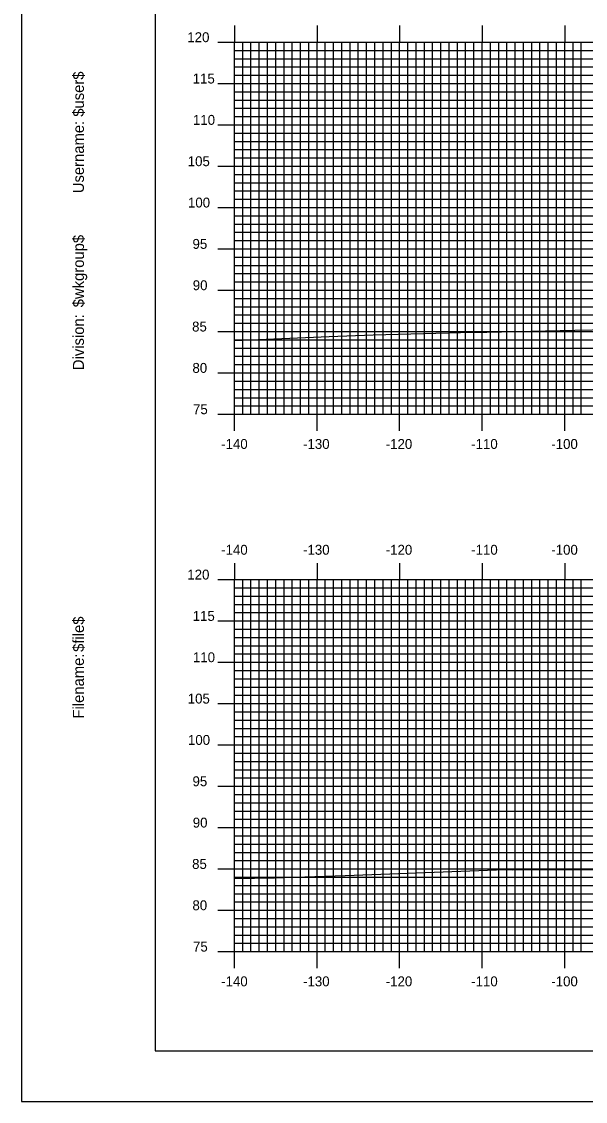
# Model space of a CAD drawing. Extents: x 485 to 829, y -1658 to -1438.
# Drawn here: x 485.3 to 553.6, y -1657.7 to -1527.1 of the extents above; entities that cross this region are included whole.
import ezdxf

# ---------------------------------------------------------------- set-up
doc = ezdxf.new("R2010")
doc.units = 0
for name, color, linetype in [('BORDER', 7, 'Continuous'), ('H_V ANNOTATION', 7, 'Continuous'), ('MAJOR', 7, 'Continuous'), ('MINOR', 7, 'Continuous'), ('PLOT BOUNDARY', 7, 'Continuous'), ('S_Roadway_Centerline', 7, 'Continuous')]:
    doc.layers.add(name, color=color, linetype=linetype)

msp = doc.modelspace()

# ---------------------------------------------------------------- linework, layer by layer
at = {"layer": 'BORDER'}
msp.add_lwpolyline([(501.53, -1651.6), (821.53, -1651.6), (821.53, -1441.6), (501.53, -1441.6)], close=True, dxfattribs=at)
at = {"layer": 'MAJOR'}
for p, q in [((511.13, -1527.6), (511.13, -1529.6)), ((521.13, -1527.6), (521.13, -1529.6)), ((531.13, -1527.6), (531.13, -1529.6)), ((541.13, -1527.6), (541.13, -1529.6)), ((551.13, -1527.6), (551.13, -1529.6)), ((509.13, -1529.6), (511.13, -1529.6)), ((511.13, -1529.6), (791.13, -1529.6)), ((511.13, -1574.6), (511.13, -1529.6)), ((511.13, -1574.6), (511.13, -1529.6)), ((511.13, -1529.6), (791.13, -1529.6)), ((521.13, -1574.6), (521.13, -1529.6)), ((531.13, -1574.6), (531.13, -1529.6)), ((541.13, -1574.6), (541.13, -1529.6)), ((551.13, -1574.6), (551.13, -1529.6)), ((509.13, -1534.6), (511.13, -1534.6)), ((511.13, -1534.6), (791.13, -1534.6)), ((509.13, -1539.6), (511.13, -1539.6)), ((511.13, -1539.6), (791.13, -1539.6)), ((509.13, -1544.6), (511.13, -1544.6)), ((511.13, -1544.6), (791.13, -1544.6)), ((509.13, -1549.6), (511.13, -1549.6)), ((511.13, -1549.6), (791.13, -1549.6)), ((509.13, -1554.6), (511.13, -1554.6)), ((511.13, -1554.6), (791.13, -1554.6)), ((509.13, -1559.6), (511.13, -1559.6)), ((511.13, -1559.6), (791.13, -1559.6)), ((509.13, -1564.6), (511.13, -1564.6)), ((511.13, -1564.6), (791.13, -1564.6)), ((509.13, -1569.6), (511.13, -1569.6)), ((511.13, -1569.6), (791.13, -1569.6)), ((509.13, -1574.6), (511.13, -1574.6)), ((511.13, -1574.6), (791.13, -1574.6)), ((511.13, -1574.6), (791.13, -1574.6)), ((511.13, -1576.61), (511.13, -1574.6)), ((521.13, -1576.61), (521.13, -1574.6)), ((531.13, -1576.61), (531.13, -1574.6)), ((541.13, -1576.61), (541.13, -1574.6)), ((551.13, -1576.61), (551.13, -1574.6)), ((511.13, -1592.6), (511.13, -1594.6)), ((521.13, -1592.6), (521.13, -1594.6)), ((531.13, -1592.6), (531.13, -1594.6)), ((541.13, -1592.6), (541.13, -1594.6)), ((551.13, -1592.6), (551.13, -1594.6)), ((509.13, -1594.6), (511.13, -1594.6)), ((511.13, -1594.6), (791.13, -1594.6)), ((511.13, -1639.6), (511.13, -1594.6)), ((511.13, -1639.6), (511.13, -1594.6)), ((511.13, -1594.6), (791.13, -1594.6)), ((521.13, -1639.6), (521.13, -1594.6)), ((531.13, -1639.6), (531.13, -1594.6)), ((541.13, -1639.6), (541.13, -1594.6)), ((551.13, -1639.6), (551.13, -1594.6)), ((509.13, -1599.6), (511.13, -1599.6)), ((511.13, -1599.6), (791.13, -1599.6)), ((509.13, -1604.6), (511.13, -1604.6)), ((511.13, -1604.6), (791.13, -1604.6)), ((509.13, -1609.6), (511.13, -1609.6)), ((511.13, -1609.6), (791.13, -1609.6)), ((509.13, -1614.6), (511.13, -1614.6)), ((511.13, -1614.6), (791.13, -1614.6)), ((509.13, -1619.6), (511.13, -1619.6)), ((511.13, -1619.6), (791.13, -1619.6)), ((509.13, -1624.6), (511.13, -1624.6)), ((511.13, -1624.6), (791.13, -1624.6)), ((509.13, -1629.6), (511.13, -1629.6)), ((511.13, -1629.6), (791.13, -1629.6)), ((509.13, -1634.6), (511.13, -1634.6)), ((511.13, -1634.6), (791.13, -1634.6)), ((509.13, -1639.6), (511.13, -1639.6)), ((511.13, -1639.6), (791.13, -1639.6)), ((511.13, -1639.6), (791.13, -1639.6)), ((511.13, -1641.61), (511.13, -1639.6)), ((521.13, -1641.61), (521.13, -1639.6)), ((531.13, -1641.61), (531.13, -1639.6)), ((541.13, -1641.61), (541.13, -1639.6)), ((551.13, -1641.61), (551.13, -1639.6))]:
    msp.add_line(p, q, dxfattribs=at)
at = {"layer": 'MINOR'}
for p, q in [((511.13, -1530.6), (791.13, -1530.6)), ((511.13, -1530.6), (513.14, -1530.6)), ((512.13, -1574.6), (512.13, -1529.6)), ((513.13, -1574.6), (513.13, -1529.6)), ((514.13, -1574.6), (514.13, -1529.6)), ((515.13, -1574.6), (515.13, -1529.6)), ((516.13, -1574.6), (516.13, -1529.6)), ((517.13, -1574.6), (517.13, -1529.6)), ((518.13, -1574.6), (518.13, -1529.6)), ((519.13, -1574.6), (519.13, -1529.6)), ((520.13, -1574.6), (520.13, -1529.6)), ((522.13, -1574.6), (522.13, -1529.6)), ((523.13, -1574.6), (523.13, -1529.6)), ((524.13, -1574.6), (524.13, -1529.6)), ((525.13, -1574.6), (525.13, -1529.6)), ((526.13, -1574.6), (526.13, -1529.6)), ((527.13, -1574.6), (527.13, -1529.6)), ((528.13, -1574.6), (528.13, -1529.6)), ((529.13, -1574.6), (529.13, -1529.6)), ((530.13, -1574.6), (530.13, -1529.6)), ((532.13, -1574.6), (532.13, -1529.6)), ((533.13, -1574.6), (533.13, -1529.6)), ((534.13, -1574.6), (534.13, -1529.6)), ((535.13, -1574.6), (535.13, -1529.6)), ((536.13, -1574.6), (536.13, -1529.6)), ((537.13, -1574.6), (537.13, -1529.6)), ((538.13, -1574.6), (538.13, -1529.6)), ((539.13, -1574.6), (539.13, -1529.6)), ((540.13, -1574.6), (540.13, -1529.6)), ((542.13, -1574.6), (542.13, -1529.6)), ((543.13, -1574.6), (543.13, -1529.6)), ((544.13, -1574.6), (544.13, -1529.6)), ((545.13, -1574.6), (545.13, -1529.6)), ((546.13, -1574.6), (546.13, -1529.6)), ((547.13, -1574.6), (547.13, -1529.6)), ((548.13, -1574.6), (548.13, -1529.6)), ((549.13, -1574.6), (549.13, -1529.6)), ((550.13, -1574.6), (550.13, -1529.6)), ((552.13, -1574.6), (552.13, -1529.6)), ((553.13, -1574.6), (553.13, -1529.6)), ((511.13, -1531.6), (791.13, -1531.6)), ((511.13, -1531.6), (513.14, -1531.6)), ((511.13, -1532.6), (791.13, -1532.6)), ((511.13, -1532.6), (513.14, -1532.6)), ((511.13, -1533.6), (791.13, -1533.6)), ((511.13, -1533.6), (513.14, -1533.6)), ((511.13, -1535.6), (791.13, -1535.6)), ((511.13, -1535.6), (513.14, -1535.6)), ((511.13, -1536.6), (791.13, -1536.6)), ((511.13, -1536.6), (513.14, -1536.6)), ((511.13, -1537.6), (791.13, -1537.6)), ((511.13, -1537.6), (513.14, -1537.6)), ((511.13, -1538.6), (791.13, -1538.6)), ((511.13, -1538.6), (513.14, -1538.6)), ((511.13, -1540.6), (791.13, -1540.6)), ((511.13, -1540.6), (513.14, -1540.6)), ((511.13, -1541.6), (791.13, -1541.6)), ((511.13, -1541.6), (513.14, -1541.6)), ((511.13, -1542.6), (791.13, -1542.6)), ((511.13, -1542.6), (513.14, -1542.6)), ((511.13, -1543.6), (791.13, -1543.6)), ((511.13, -1543.6), (513.14, -1543.6)), ((511.13, -1545.6), (791.13, -1545.6)), ((511.13, -1545.6), (513.14, -1545.6)), ((511.13, -1546.6), (791.13, -1546.6)), ((511.13, -1546.6), (513.14, -1546.6)), ((511.13, -1547.6), (791.13, -1547.6)), ((511.13, -1547.6), (513.14, -1547.6)), ((511.13, -1548.6), (791.13, -1548.6)), ((511.13, -1548.6), (513.14, -1548.6)), ((511.13, -1550.6), (791.13, -1550.6)), ((511.13, -1550.6), (513.14, -1550.6)), ((511.13, -1551.6), (791.13, -1551.6)), ((511.13, -1551.6), (513.14, -1551.6)), ((511.13, -1552.6), (791.13, -1552.6)), ((511.13, -1552.6), (513.14, -1552.6)), ((511.13, -1553.6), (791.13, -1553.6)), ((511.13, -1553.6), (513.14, -1553.6)), ((511.13, -1555.6), (791.13, -1555.6)), ((511.13, -1555.6), (513.14, -1555.6)), ((511.13, -1556.6), (791.13, -1556.6)), ((511.13, -1556.6), (513.14, -1556.6)), ((511.13, -1557.6), (791.13, -1557.6)), ((511.13, -1557.6), (513.14, -1557.6)), ((511.13, -1558.6), (791.13, -1558.6)), ((511.13, -1558.6), (513.14, -1558.6)), ((511.13, -1560.6), (791.13, -1560.6)), ((511.13, -1560.6), (513.14, -1560.6)), ((511.13, -1561.6), (791.13, -1561.6)), ((511.13, -1561.6), (513.14, -1561.6)), ((511.13, -1562.6), (791.13, -1562.6)), ((511.13, -1562.6), (513.14, -1562.6)), ((511.13, -1563.6), (791.13, -1563.6)), ((511.13, -1563.6), (513.14, -1563.6)), ((511.13, -1565.6), (791.13, -1565.6)), ((511.13, -1565.6), (513.14, -1565.6)), ((511.13, -1566.6), (791.13, -1566.6)), ((511.13, -1566.6), (513.14, -1566.6)), ((511.13, -1567.6), (791.13, -1567.6)), ((511.13, -1567.6), (513.14, -1567.6)), ((511.13, -1568.6), (791.13, -1568.6)), ((511.13, -1568.6), (513.14, -1568.6)), ((511.13, -1570.6), (791.13, -1570.6)), ((511.13, -1570.6), (513.14, -1570.6)), ((511.13, -1571.6), (791.13, -1571.6)), ((511.13, -1571.6), (513.14, -1571.6)), ((511.13, -1572.6), (791.13, -1572.6)), ((511.13, -1572.6), (513.14, -1572.6)), ((511.13, -1573.6), (791.13, -1573.6)), ((511.13, -1573.6), (513.14, -1573.6)), ((512.13, -1639.6), (512.13, -1594.6)), ((513.13, -1639.6), (513.13, -1594.6)), ((514.13, -1639.6), (514.13, -1594.6)), ((515.13, -1639.6), (515.13, -1594.6)), ((516.13, -1639.6), (516.13, -1594.6)), ((517.13, -1639.6), (517.13, -1594.6)), ((518.13, -1639.6), (518.13, -1594.6)), ((519.13, -1639.6), (519.13, -1594.6)), ((520.13, -1639.6), (520.13, -1594.6)), ((522.13, -1639.6), (522.13, -1594.6)), ((523.13, -1639.6), (523.13, -1594.6)), ((524.13, -1639.6), (524.13, -1594.6)), ((525.13, -1639.6), (525.13, -1594.6)), ((526.13, -1639.6), (526.13, -1594.6)), ((527.13, -1639.6), (527.13, -1594.6)), ((528.13, -1639.6), (528.13, -1594.6)), ((529.13, -1639.6), (529.13, -1594.6)), ((530.13, -1639.6), (530.13, -1594.6)), ((532.13, -1639.6), (532.13, -1594.6)), ((533.13, -1639.6), (533.13, -1594.6)), ((534.13, -1639.6), (534.13, -1594.6)), ((535.13, -1639.6), (535.13, -1594.6)), ((536.13, -1639.6), (536.13, -1594.6)), ((537.13, -1639.6), (537.13, -1594.6)), ((538.13, -1639.6), (538.13, -1594.6)), ((539.13, -1639.6), (539.13, -1594.6)), ((540.13, -1639.6), (540.13, -1594.6)), ((542.13, -1639.6), (542.13, -1594.6)), ((543.13, -1639.6), (543.13, -1594.6)), ((544.13, -1639.6), (544.13, -1594.6)), ((545.13, -1639.6), (545.13, -1594.6)), ((546.13, -1639.6), (546.13, -1594.6)), ((547.13, -1639.6), (547.13, -1594.6)), ((548.13, -1639.6), (548.13, -1594.6)), ((549.13, -1639.6), (549.13, -1594.6)), ((550.13, -1639.6), (550.13, -1594.6)), ((552.13, -1639.6), (552.13, -1594.6)), ((553.13, -1639.6), (553.13, -1594.6)), ((511.13, -1595.6), (791.13, -1595.6)), ((511.13, -1595.6), (513.14, -1595.6)), ((511.13, -1596.6), (791.13, -1596.6)), ((511.13, -1596.6), (513.14, -1596.6)), ((511.13, -1597.6), (791.13, -1597.6)), ((511.13, -1597.6), (513.14, -1597.6)), ((511.13, -1598.6), (791.13, -1598.6)), ((511.13, -1598.6), (513.14, -1598.6)), ((511.13, -1600.6), (791.13, -1600.6)), ((511.13, -1600.6), (513.14, -1600.6)), ((511.13, -1601.6), (791.13, -1601.6)), ((511.13, -1601.6), (513.14, -1601.6)), ((511.13, -1602.6), (791.13, -1602.6)), ((511.13, -1602.6), (513.14, -1602.6)), ((511.13, -1603.6), (791.13, -1603.6)), ((511.13, -1603.6), (513.14, -1603.6)), ((511.13, -1605.6), (791.13, -1605.6)), ((511.13, -1605.6), (513.14, -1605.6)), ((511.13, -1606.6), (791.13, -1606.6)), ((511.13, -1606.6), (513.14, -1606.6)), ((511.13, -1607.6), (791.13, -1607.6)), ((511.13, -1607.6), (513.14, -1607.6)), ((511.13, -1608.6), (791.13, -1608.6)), ((511.13, -1608.6), (513.14, -1608.6)), ((511.13, -1610.6), (791.13, -1610.6)), ((511.13, -1610.6), (513.14, -1610.6)), ((511.13, -1611.6), (791.13, -1611.6)), ((511.13, -1611.6), (513.14, -1611.6)), ((511.13, -1612.6), (791.13, -1612.6)), ((511.13, -1612.6), (513.14, -1612.6)), ((511.13, -1613.6), (791.13, -1613.6)), ((511.13, -1613.6), (513.14, -1613.6)), ((511.13, -1615.6), (791.13, -1615.6)), ((511.13, -1615.6), (513.14, -1615.6)), ((511.13, -1616.6), (791.13, -1616.6)), ((511.13, -1616.6), (513.14, -1616.6)), ((511.13, -1617.6), (791.13, -1617.6)), ((511.13, -1617.6), (513.14, -1617.6)), ((511.13, -1618.6), (791.13, -1618.6)), ((511.13, -1618.6), (513.14, -1618.6)), ((511.13, -1620.6), (791.13, -1620.6)), ((511.13, -1620.6), (513.14, -1620.6)), ((511.13, -1621.6), (791.13, -1621.6)), ((511.13, -1621.6), (513.14, -1621.6)), ((511.13, -1622.6), (791.13, -1622.6)), ((511.13, -1622.6), (513.14, -1622.6)), ((511.13, -1623.6), (791.13, -1623.6)), ((511.13, -1623.6), (513.14, -1623.6)), ((511.13, -1625.6), (791.13, -1625.6)), ((511.13, -1625.6), (513.14, -1625.6)), ((511.13, -1626.6), (791.13, -1626.6)), ((511.13, -1626.6), (513.14, -1626.6)), ((511.13, -1627.6), (791.13, -1627.6)), ((511.13, -1627.6), (513.14, -1627.6)), ((511.13, -1628.6), (791.13, -1628.6)), ((511.13, -1628.6), (513.14, -1628.6)), ((511.13, -1630.6), (791.13, -1630.6)), ((511.13, -1630.6), (513.14, -1630.6)), ((511.13, -1631.6), (791.13, -1631.6)), ((511.13, -1631.6), (513.14, -1631.6)), ((511.13, -1632.6), (791.13, -1632.6)), ((511.13, -1632.6), (513.14, -1632.6)), ((511.13, -1633.6), (791.13, -1633.6)), ((511.13, -1633.6), (513.14, -1633.6)), ((511.13, -1635.6), (791.13, -1635.6)), ((511.13, -1635.6), (513.14, -1635.6)), ((511.13, -1636.6), (791.13, -1636.6)), ((511.13, -1636.6), (513.14, -1636.6)), ((511.13, -1637.6), (791.13, -1637.6)), ((511.13, -1637.6), (513.14, -1637.6)), ((511.13, -1638.6), (791.13, -1638.6)), ((511.13, -1638.6), (513.14, -1638.6))]:
    msp.add_line(p, q, dxfattribs=at)
at = {"layer": 'PLOT BOUNDARY'}
msp.add_lwpolyline([(485.35, -1657.72), (825.35, -1657.72), (825.35, -1437.72), (485.35, -1437.72)], close=True, dxfattribs=at)
at = {"layer": 'S_Roadway_Centerline'}
for points in [[(511.13, -1565.67), (522.61, -1565.21), (527.92, -1564.98), (537.05, -1564.77), (540, -1564.68), (541.68, -1564.68), (552.34, -1564.43), (560.82, -1564.28), (564.84, -1564.2), (571.8, -1563.91), (579.14, -1563.58), (588.25, -1563.29), (597.66, -1563.2), (600.37, -1563.13), (604.91, -1562.98), (615.91, -1562.69), (624.29, -1562.57)], [(511.13, -1630.76), (515.97, -1630.68), (524.55, -1630.38), (542.88, -1629.72), (544.02, -1629.69), (544.86, -1629.7), (550.35, -1629.68), (565.48, -1629.71), (570.93, -1629.57), (578.45, -1629.33), (585.05, -1629.28), (590.98, -1629.12), (598.18, -1629.1), (605.63, -1629.02), (614.3, -1628.78), (626.36, -1628.86)]]:
    msp.add_lwpolyline(points, dxfattribs=at)

# ---------------------------------------------------------------- texts
at = {"layer": 'BORDER'}
for s, p in [('$user$', (492.9, -1538.62)), ('Username:', (492.9, -1547.87)), ('$wkgroup$', (492.9, -1561.67)), ('Division:', (492.9, -1569.27)), ('$file$', (492.9, -1603.35)), ('Filename:', (492.9, -1611.41))]:
    msp.add_text(s, height=1.339, rotation=90, dxfattribs=at).set_placement(p)
at = {"layer": 'H_V ANNOTATION'}
for s, p in [('120', (505.42, -1529.6)), ('115', (506.07, -1534.6)), ('110', (506.1, -1539.6)), ('105', (505.47, -1544.6)), ('100', (505.5, -1549.6)), ('95', (506.05, -1554.6)), ('90', (506.08, -1559.6)), ('85', (506, -1564.6)), ('80', (506.04, -1569.6)), ('75', (506.11, -1574.6)), ('-140', (509.52, -1578.8)), ('-130', (519.44, -1578.8)), ('-120', (529.45, -1578.8)), ('-110', (539.8, -1578.8)), ('-100', (549.5, -1578.8)), ('-140', (509.52, -1591.6)), ('-130', (519.44, -1591.6)), ('-120', (529.45, -1591.6)), ('-110', (539.8, -1591.6)), ('-100', (549.5, -1591.6)), ('120', (505.42, -1594.6)), ('115', (506.07, -1599.6)), ('110', (506.1, -1604.6)), ('105', (505.47, -1609.6)), ('100', (505.5, -1614.6)), ('95', (506.05, -1619.6)), ('90', (506.08, -1624.6)), ('85', (506, -1629.6)), ('80', (506.04, -1634.6)), ('75', (506.11, -1639.6)), ('-140', (509.52, -1643.8)), ('-130', (519.44, -1643.8)), ('-120', (529.45, -1643.8)), ('-110', (539.8, -1643.8)), ('-100', (549.5, -1643.8))]:
    msp.add_text(s, height=1.2, dxfattribs=at).set_placement(p)
at = {"layer": 'MAJOR'}
for p in [(511.13, -1574.6), (511.13, -1639.6)]:
    msp.add_text('-', height=0.012, dxfattribs=at).set_placement(p)

doc.saveas('drawing.dxf')
